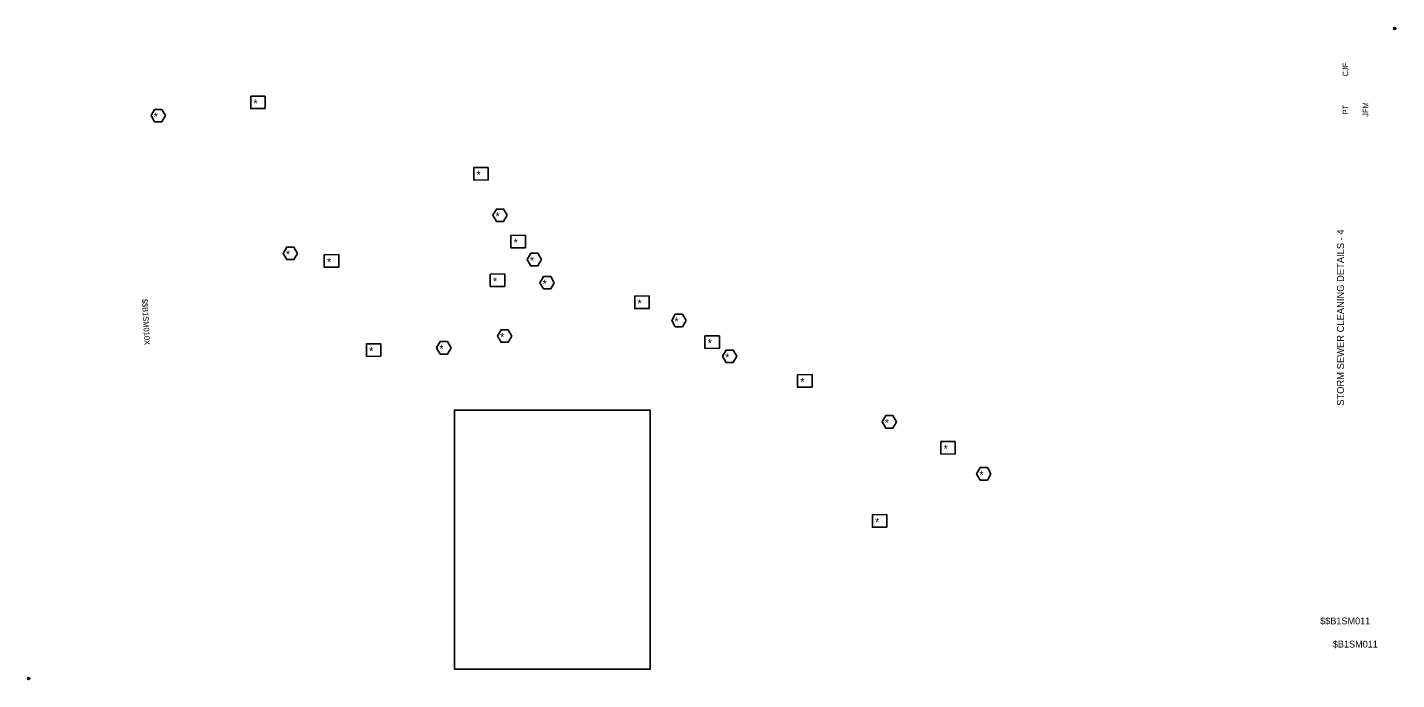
# Model space of a CAD drawing. Extents: x -0.1 to 34.1, y 0.3 to 16.6.
import ezdxf

# ---------------------------------------------------------------- set-up
doc = ezdxf.new("R2010")
doc.units = 0
for name, color, linetype in [('Default', 7, 'Continuous'), ('SC_Scratch1', 7, 'Continuous'), ('SH_Data', 7, 'Continuous')]:
    doc.layers.add(name, color=color, linetype=linetype)

msp = doc.modelspace()

# ---------------------------------------------------------------- linework, layer by layer
at = {"layer": 'Default'}
for p, q in [((34.035, 16.552), (34.087, 16.552)), ((34.062, 16.552), (34.111, 16.552)), ((-0.114, 0.31), (-0.062, 0.31)), ((-0.088, 0.31), (-0.039, 0.31))]:
    msp.add_line(p, q, dxfattribs=at)
msp.add_lwpolyline([(10.561, 0.544), (15.457, 0.544), (15.457, 7.019), (10.561, 7.019)], close=True, dxfattribs=at)
for centre in [(34.061, 16.552), (-0.088, 0.31)]:
    msp.add_circle(centre, 0.026, dxfattribs=at)
at = {"layer": 'SC_Scratch1'}
for points in [[(5.829, 14.864), (5.469, 14.86), (5.469, 14.548), (5.829, 14.552)], [(3.336, 14.375), (3.246, 14.53), (3.066, 14.53), (2.976, 14.375), (3.066, 14.219), (3.246, 14.219)], [(11.405, 13.08), (11.045, 13.076), (11.045, 12.764), (11.405, 12.768)], [(11.88, 11.886), (11.79, 12.041), (11.61, 12.041), (11.52, 11.886), (11.61, 11.73), (11.79, 11.73)], [(12.333, 11.386), (11.974, 11.382), (11.974, 11.07), (12.333, 11.074)], [(6.639, 10.932), (6.549, 11.088), (6.369, 11.088), (6.279, 10.932), (6.369, 10.776), (6.549, 10.776)], [(7.667, 10.901), (7.307, 10.897), (7.307, 10.585), (7.667, 10.589)], [(12.739, 10.779), (12.649, 10.934), (12.469, 10.934), (12.379, 10.779), (12.469, 10.623), (12.649, 10.623)], [(11.817, 10.42), (11.457, 10.416), (11.457, 10.105), (11.817, 10.109)], [(13.057, 10.199), (12.967, 10.355), (12.788, 10.355), (12.698, 10.199), (12.788, 10.043), (12.967, 10.043)], [(15.428, 9.87), (15.069, 9.866), (15.069, 9.555), (15.428, 9.559)], [(16.351, 9.257), (16.261, 9.413), (16.081, 9.413), (15.991, 9.257), (16.081, 9.101), (16.261, 9.101)], [(11.997, 8.868), (11.907, 9.024), (11.727, 9.024), (11.637, 8.868), (11.727, 8.712), (11.907, 8.712)], [(8.72, 8.674), (8.361, 8.67), (8.361, 8.359), (8.72, 8.363)], [(10.475, 8.573), (10.385, 8.729), (10.205, 8.729), (10.115, 8.573), (10.205, 8.417), (10.385, 8.417)], [(17.183, 8.874), (16.823, 8.87), (16.823, 8.558), (17.183, 8.562)], [(17.619, 8.361), (17.529, 8.517), (17.349, 8.517), (17.259, 8.361), (17.349, 8.205), (17.529, 8.205)], [(19.499, 7.905), (19.139, 7.901), (19.139, 7.59), (19.499, 7.594)], [(21.61, 6.723), (21.52, 6.879), (21.34, 6.879), (21.25, 6.723), (21.34, 6.567), (21.52, 6.567)], [(23.079, 6.236), (22.72, 6.232), (22.72, 5.92), (23.079, 5.924)], [(23.972, 5.423), (23.882, 5.579), (23.702, 5.579), (23.613, 5.423), (23.702, 5.267), (23.882, 5.267)], [(21.368, 4.405), (21.009, 4.402), (21.009, 4.09), (21.368, 4.094)]]:
    msp.add_lwpolyline(points, close=True, dxfattribs=at)

# ---------------------------------------------------------------- texts
at = {"layer": 'Default'}
for s, p in [('####', (34.057, 16.542)), ('2', (34.06, 16.559)), ('Ref-1', (34.094, 16.559)), ('Engr 1:1', (34.094, 16.542)), ('####', (-0.093, 0.3)), ('1', (-0.089, 0.317)), ('Drawing', (-0.055, 0.317)), ('Engr 1:1', (-0.055, 0.3))]:
    msp.add_text(s, height=0.00328, dxfattribs=at).set_placement(p)
at = {"layer": 'SC_Scratch1'}
for p in [(5.536, 14.579), (3.043, 14.25), (11.112, 12.795), (11.587, 11.761), (12.041, 11.102), (6.346, 10.808), (7.374, 10.617), (12.447, 10.654), (11.524, 10.136), (12.765, 10.074), (15.136, 9.586), (16.058, 9.132), (11.704, 8.743), (8.428, 8.39), (10.182, 8.449), (16.89, 8.59), (17.326, 8.236), (19.206, 7.621), (21.317, 6.598), (22.787, 5.952), (23.68, 5.298), (21.076, 4.121)]:
    msp.add_text('*', height=0.2, dxfattribs=at).set_placement(p)
msp.add_text('$$B1SM010X', height=0.14, rotation=273.002, dxfattribs=at).set_placement((2.751, 9.794))
at = {"layer": 'SH_Data'}
for s, height, p in [('CJF', 0.14, (32.903, 15.353)), ('PT', 0.14, (32.903, 14.401)), ('JFM', 0.14, (33.403, 14.344)), ('STORM SEWER CLEANING DETAILS - 4', 0.175, (32.796, 7.125))]:
    msp.add_text(s, height=height, rotation=90, dxfattribs=at).set_placement(p)
for s, p in [('$$B1SM011', (32.201, 1.665)), ('$B1SM011', (32.517, 1.085))]:
    msp.add_text(s, height=0.17, dxfattribs=at).set_placement(p)

doc.saveas('drawing.dxf')
